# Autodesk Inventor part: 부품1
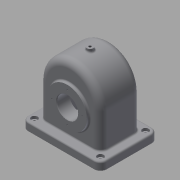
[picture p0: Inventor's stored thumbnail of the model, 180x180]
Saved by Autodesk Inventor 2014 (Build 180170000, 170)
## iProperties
Created: 2016-10
Part Number: 부품1
Material: 일반
Document SubType Name: Modeling
Designer: SCD-A13
Density: 1 g/cm^3
Appearance: 기본값
Author: SCD-A13
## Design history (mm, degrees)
sketch "스케치1"
  geometry: L1 (75, 55)-(-75, 55); L2 (-75, 55)-(-75, -55); L3 (-75, -55)-(75, -55); L4 (75, -55)-(75, 55); L5 (75, 55)-(-75, -55); L6 (-75, 55)-(75, -55); 1 further point
  constraints: 12 end point, 2 midpoint, 2 parallel, 1 horizontal, 1 perpendicular
  dimensions: "d0" = 150 distance of L2.end L3.end; "d1" = 110 distance of L3.end L1.start
extrude "돌출1" new body sketch "스케치1" distance "d2" = 15; taper "d3" = 0 deg
sketch "스케치2"
  geometry: L1 (75, 15)-(-75, 15) reference; L2 (-58, 80)-(-58, 15); L3 (-75, 0)-(-75, 15) reference; L4 (58, 80)-(58, 15); L5 (75, 0)-(-75, 0) reference; A1 r 58 centre (0, 80) between (-58, 80) and (58, 80); 2 further points
  constraints: 4 end point, 2 point on circle, 2 point on line, 2 tangent, 1 centre point, 1 midpoint, 1 parallel, 1 perpendicular, 1 vertical alignment
  dimensions: "d4" = 116 diameter of A1; "d5" = 80 distance from line of L5 A1.centre
extrude "돌출2" join sketch "스케치2" stored distance "d6" = 77; taper "d7" = 0 deg
fillet "모깎기1" dims "d8" = 13
sketch "스케치3"
  geometry: L1 (52, 80)-(52, 0); L2 (-52, 80)-(-52, 0); L3 (-58, 15)-(-58, 80) reference; L4 (-52, 0)-(52, 0); L5 (75, 0)-(-75, 0) reference; A1 r 52 centre (0, 80) between (52, 80) and (-52, 80); A2 r 58 centre (0, 80) between (58, 80) and (-58, 80) reference; 1 further point
  constraints: 6 end point, 2 point on circle, 2 tangent, 1 centre point, 1 coincident, 1 collinear, 1 parallel, 1 perpendicular, 1 vertical, 1 vertical alignment
  dimensions: "d9" = 104 diameter of A1
extrude "돌출3" cut sketch "스케치3" stored distance "d11" = 67; taper "d12" = 0 deg
fillet "모깎기2" dims "d13" = 8
node "작업 평면1"
sketch "스케치4"
  geometry: C1 r 28 at (0, 65); 1 further point
  constraints: 1 centre point
  dimensions: "d15" = 56 diameter of C1; "d16" = 65 distance of point (0, 0) C1.centre
extrude "돌출4" join sketch "스케치4" stored distance "d17" = 67; taper "d18" = 40 deg
sketch "스케치5"
  geometry: L1 (-75, 0)-(75, 0) reference; C1 r 37.5 at (0, 65); 1 further point
  constraints: 1 centre point
  dimensions: "d19" = 75 diameter of C1; "d20" = 65 distance from line of L1 C1.centre
extrude "돌출5" join sketch "스케치5" distance "d21" = 5; taper "d22" = 0 deg
sketch "스케치6"
  geometry: L1 (-75, 0)-(75, 0) reference; C1 r 32.5 at (0, 65); 1 further point
  constraints: 1 centre point
  dimensions: "d23" = 65 diameter of C1; "d24" = 65 distance from line of L1 C1.centre
extrude "돌출6" join sketch "스케치6" distance "d25" = 10; taper "d26" = 0 deg
hole "구멍1" diameter "d29" = 40; stored, may be unused: countersink angle "d33" = 90 deg, drill point angle "d35" = 118 deg; dims "d27" = 10, "d28" = 10, "d30" = 6, "d31" = 4, "d32" = 2, "d34" = 8
node "작업 평면2"
sketch "스케치8"
  geometry: C1 r 6 at (0, 0); 1 further point
  constraints: 1 centre point, 1 coincident
  dimensions: "d37" = 12 diameter of C1
extrude "돌출7" join sketch "스케치8" stored distance "d38" = 10; taper "d39" = 0 deg
fillet "모깎기3" dims "d40" = 3
hole "구멍2" diameter "d43" = 4.459; stored, may be unused: countersink angle "d47" = 90 deg, drill point angle "d49" = 118 deg; dims "d41" = 10, "d42" = 10, "d44" = 6, "d45" = 4, "d46" = 2, "d48" = 8
chamfer "모따기1" distance "d50" = 1; stored, may be unused: second distance "d51" = 2, angle "d52" = 45 deg
fillet "모깎기4" dims "d53" = 12
fillet "모깎기5" dims "d54" = 3
sketch "스케치9"
  geometry: A1 r 9 centre (-63, 43) between (-63, 52) and (-72, 43) reference; A2 r 9 centre (-63, -43) between (-72, -43) and (-63, -52) reference; A3 r 9 centre (63, -43) between (63, -52) and (72, -43) reference; A4 r 9 centre (63, 43) between (72, 43) and (63, 52) reference; 5 further points
  constraints: 4 coincident
hole "구멍3" sketch "스케치9" at (-63, 43), (63, 43), (63, -43), (-63, -43) diameter "d55" = 5; stored, may be unused: countersink angle "d59" = 90 deg, drill point angle "d61" = 118 deg; dims "d56" = 6, "d57" = 12, "d58" = 5, "d60" = 8
sketch "스케치10" dims "d62" = 52
  geometry: C1 r 32.5 at (0, 0) reference; C2 r 21 at (0, 0) reference; 3 further points
  constraints: 2 vertical alignment, 1 coincident, 2 other
hole "구멍4" sketch "스케치10" at (0, 26) diameter "d63" = 2.459; stored, may be unused: countersink angle "d67" = 90 deg, drill point angle "d69" = 118 deg; dims "d64" = 6, "d65" = 12, "d66" = 5, "d68" = 8
sketch "스케치11" dims "d73" = 58
  geometry: C1 r 37.5 at (0, 0) reference; C2 r 21 at (0, 0) reference; 3 further points
  constraints: 2 vertical alignment, 1 coincident, 2 other
hole "구멍5" sketch "스케치11" at (0, 29) diameter "d74" = 2.459; stored, may be unused: countersink angle "d78" = 90 deg, drill point angle "d80" = 118 deg; dims "d75" = 6, "d76" = 12, "d77" = 5, "d79" = 8
node "솔리드1"
pattern_circular "원형 패턴1" dims angle "d71" = 360 deg
pattern_circular "원형 패턴2" dims angle "d82" = 360 deg
other parameters: "d14" = 14, "d36" = 144
